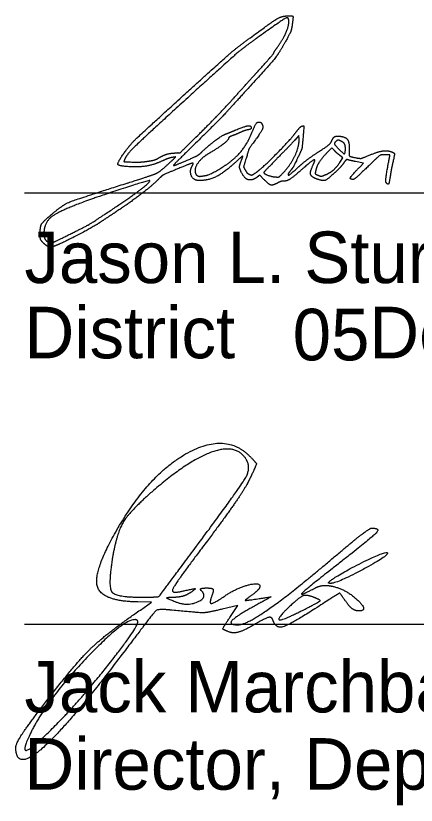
# Model space of a CAD drawing. Extents: x 0 to 34, y 0 to 22.
# Drawn here: x 24.504 to 25.591, y 6.891 to 9.036 of the extents above; entities that cross this region are included whole.
import ezdxf

# ---------------------------------------------------------------- set-up
doc = ezdxf.new("R2010")
doc.units = 0
doc.layers.add('SH_Data', color=7, linetype='Continuous')
doc.layers.add('SH_Text', color=7, linetype='Continuous')

msp = doc.modelspace()

# ---------------------------------------------------------------- linework, layer by layer
at = {"layer": 'SH_Data'}
for p, q in [((24.5279, 8.555), (28.0279, 8.555)), ((24.5279, 7.3828), (28.0279, 7.3828))]:
    msp.add_line(p, q, dxfattribs=at)
for points in [[(25.2734, 8.7013), (25.273, 8.7106), (25.2619, 8.698)], [(25.3691, 8.6693), (25.3619, 8.6764), (25.3504, 8.6648)], [(25.3841, 8.6372), (25.3926, 8.6498), (25.3844, 8.656)], [(25.4388, 8.6256), (25.4485, 8.6356), (25.4269, 8.6396)], [(25.1778, 8.5911), (25.1667, 8.6023), (25.1597, 8.5972)]]:
    msp.add_lwpolyline(points, dxfattribs=at)
for points in [[(25.1411, 8.976), (25.2022, 9.0209), (25.2243, 9.0342), (25.2391, 9.0353)], [(25.2391, 9.0353), (25.2552, 9.0364), (25.2579, 9.0321), (25.2546, 9.0104)], [(25.2456, 9.0172), (25.2463, 9.0338), (25.2292, 9.0255), (25.1595, 8.9754)], [(25.2164, 8.9529), (25.2294, 8.9713), (25.2451, 9.0058), (25.2456, 9.0172)], [(25.2546, 9.0104), (25.2526, 8.9974), (25.2484, 8.9869), (25.2367, 8.9657)], [(24.9691, 8.8279), (25.0673, 8.9172), (25.1035, 8.9484), (25.1411, 8.976)], [(25.1595, 8.9754), (25.1187, 8.9461), (25.0918, 8.9228), (24.971, 8.8127)], [(25.2367, 8.9657), (25.2185, 8.933), (25.1947, 8.9036), (25.1193, 8.8209)], [(25.2052, 8.9357), (25.2052, 8.9365), (25.2102, 8.9443), (25.2164, 8.9529)], [(25.162, 8.8853), (25.193, 8.9196), (25.2051, 8.9338), (25.2052, 8.9357)], [(25.097, 8.8131), (25.119, 8.8375), (25.1482, 8.87), (25.162, 8.8853)], [(24.7957, 8.6591), (24.813, 8.6839), (24.8466, 8.7166), (24.9691, 8.8279)], [(25.1193, 8.8209), (25.0669, 8.7635), (25.0507, 8.7468), (24.966, 8.6635)], [(24.971, 8.8127), (24.8453, 8.698), (24.8051, 8.6585), (24.7992, 8.6437)], [(25.0037, 8.7159), (25.0331, 8.745), (25.0751, 8.7887), (25.097, 8.8131)], [(25.1021, 8.7257), (25.1264, 8.7357), (25.1438, 8.7379), (25.1435, 8.7309)], [(25.1435, 8.7309), (25.1435, 8.7289), (25.1396, 8.7266), (25.1348, 8.7258)], [(25.1415, 8.7093), (25.1539, 8.7382), (25.1595, 8.7472), (25.1653, 8.7469)], [(25.1731, 8.7411), (25.1765, 8.7339), (25.1706, 8.7202), (25.154, 8.6974)], [(25.1653, 8.7469), (25.1681, 8.7468), (25.1716, 8.7442), (25.1731, 8.7411)], [(25.2642, 8.7182), (25.2711, 8.7277), (25.2791, 8.7357), (25.2818, 8.7361)], [(25.2818, 8.7361), (25.2864, 8.7368), (25.2865, 8.735), (25.2841, 8.7058)], [(24.9393, 8.6629), (24.95, 8.6631), (24.9518, 8.6646), (25.0037, 8.7159)], [(25.0104, 8.6665), (25.025, 8.6808), (25.0633, 8.71), (25.0717, 8.7133)], [(25.0717, 8.7133), (25.0754, 8.7147), (25.089, 8.7203), (25.1021, 8.7257)], [(25.0919, 8.7096), (25.0864, 8.7076), (25.0818, 8.7042), (25.0817, 8.702)], [(25.0866, 8.6391), (25.1054, 8.6537), (25.1326, 8.6884), (25.1415, 8.7093)], [(25.114, 8.7187), (25.1074, 8.7156), (25.0974, 8.7115), (25.0919, 8.7096)], [(25.1348, 8.7258), (25.13, 8.725), (25.1207, 8.7218), (25.114, 8.7187)], [(25.1572, 8.6103), (25.1742, 8.6224), (25.2494, 8.6982), (25.2642, 8.7182)], [(25.0817, 8.702), (25.0815, 8.6976), (25.0512, 8.6746), (25.0275, 8.6609)], [(25.154, 8.6974), (25.1378, 8.6748), (25.1372, 8.6737), (25.1295, 8.6477)], [(25.2619, 8.698), (25.2558, 8.6911), (25.2344, 8.6688), (25.2143, 8.6485)], [(25.2303, 8.6089), (25.2502, 8.6297), (25.2743, 8.6813), (25.2734, 8.7013)], [(25.2841, 8.7058), (25.2819, 8.6795), (25.2803, 8.672), (25.2736, 8.6579)], [(25.3259, 8.6658), (25.3463, 8.6789), (25.3589, 8.6889), (25.3608, 8.6932)], [(25.3608, 8.6932), (25.3654, 8.7038), (25.3718, 8.7089), (25.3801, 8.7086)], [(25.3751, 8.6956), (25.3685, 8.6906), (25.3699, 8.6852), (25.3808, 8.6739)], [(25.3865, 8.6952), (25.3808, 8.698), (25.3783, 8.698), (25.3751, 8.6956)], [(25.3801, 8.7086), (25.3986, 8.7077), (25.4105, 8.692), (25.4095, 8.6694)], [(25.399, 8.6707), (25.3995, 8.6823), (25.3949, 8.6914), (25.3865, 8.6952)], [(24.9662, 8.6417), (24.9904, 8.6519), (25.0024, 8.6587), (25.0104, 8.6665)], [(25.3844, 8.656), (25.3799, 8.6594), (25.373, 8.6654), (25.3691, 8.6693)], [(25.3808, 8.6739), (25.3932, 8.661), (25.3985, 8.6601), (25.399, 8.6707)], [(25.4095, 8.6694), (25.4089, 8.6557), (25.4119, 8.6528), (25.4302, 8.6494)], [(25.4615, 8.6558), (25.4842, 8.6653), (25.5103, 8.6704), (25.5207, 8.6673)], [(25.5207, 8.6673), (25.5314, 8.6641), (25.5329, 8.6579), (25.5279, 8.6374)], [(24.8141, 8.6254), (24.7844, 8.6268), (24.7795, 8.6357), (24.7957, 8.6591)], [(24.862, 8.6403), (24.874, 8.642), (24.8866, 8.6458), (24.8922, 8.6493)], [(24.8922, 8.6493), (24.9043, 8.6567), (24.925, 8.6627), (24.9393, 8.6629)], [(24.9294, 8.6508), (24.9243, 8.6501), (24.9117, 8.6456), (24.9013, 8.6409)], [(24.9167, 8.6315), (24.9384, 8.6519), (24.9385, 8.6521), (24.9294, 8.6508)], [(24.966, 8.6635), (24.947, 8.6448), (24.9318, 8.6291), (24.9322, 8.6286)], [(25.0275, 8.6609), (25.0116, 8.6517), (24.9915, 8.6268), (24.991, 8.6158)], [(25.1201, 8.6541), (25.1194, 8.6541), (25.1111, 8.647), (25.1018, 8.6383)], [(25.1172, 8.6433), (25.1196, 8.6492), (25.1209, 8.654), (25.1201, 8.6541)], [(25.1295, 8.6477), (25.1228, 8.6252), (25.1228, 8.6247), (25.1273, 8.6162)], [(25.2143, 8.6485), (25.1943, 8.6281), (25.1778, 8.6107), (25.1778, 8.6097)], [(25.2736, 8.6579), (25.2599, 8.6289), (25.2569, 8.6233), (25.2501, 8.615)], [(25.2713, 8.6244), (25.2837, 8.6358), (25.3083, 8.6544), (25.3259, 8.6658)], [(25.3504, 8.6648), (25.3355, 8.6496), (25.3216, 8.628), (25.3188, 8.6158)], [(25.404, 8.6453), (25.4031, 8.6461), (25.3989, 8.6417), (25.3945, 8.6355)], [(25.4269, 8.6396), (25.4151, 8.6418), (25.4048, 8.6444), (25.404, 8.6453)], [(25.4302, 8.6494), (25.4395, 8.6478), (25.4448, 8.6488), (25.4615, 8.6558)], [(25.5124, 8.658), (25.4968, 8.6587), (25.4885, 8.6534), (25.4564, 8.6222)], [(25.5107, 8.5809), (25.5079, 8.5839), (25.5106, 8.6075), (25.5183, 8.6479)], [(25.5183, 8.6479), (25.5201, 8.6573), (25.5198, 8.6577), (25.5124, 8.658)], [(24.7992, 8.6437), (24.7975, 8.6396), (24.7995, 8.6391), (24.8194, 8.6382)], [(24.9013, 8.6409), (24.8791, 8.6308), (24.8415, 8.6241), (24.8141, 8.6254)], [(24.8194, 8.6382), (24.8315, 8.6377), (24.8507, 8.6386), (24.862, 8.6403)], [(24.8827, 8.6061), (24.8898, 8.609), (24.9037, 8.6194), (24.9167, 8.6315)], [(24.9322, 8.6286), (24.9327, 8.6281), (24.948, 8.634), (24.9662, 8.6417)], [(24.9858, 8.6353), (24.9852, 8.636), (24.9663, 8.629), (24.9438, 8.6197)], [(24.9998, 8.5882), (24.9859, 8.5888), (24.9755, 8.6146), (24.9836, 8.6283)], [(24.9836, 8.6283), (24.9855, 8.6314), (24.9865, 8.6346), (24.9858, 8.6353)], [(25.1018, 8.6383), (25.0706, 8.6093), (25.0254, 8.5871), (24.9998, 8.5882)], [(25.0203, 8.6018), (25.0293, 8.6033), (25.0697, 8.626), (25.0866, 8.6391)], [(25.1159, 8.6122), (25.1114, 8.6219), (25.1118, 8.6298), (25.1172, 8.6433)], [(25.2434, 8.6054), (25.2432, 8.6005), (25.2513, 8.6061), (25.2713, 8.6244)], [(25.3161, 8.643), (25.3163, 8.6469), (25.2987, 8.634), (25.2745, 8.6124)], [(25.3206, 8.5926), (25.306, 8.5981), (25.3028, 8.612), (25.3117, 8.6308)], [(25.3117, 8.6308), (25.3141, 8.6359), (25.3161, 8.6414), (25.3161, 8.643)], [(25.3447, 8.6036), (25.3584, 8.6094), (25.3746, 8.6233), (25.3841, 8.6372)], [(25.3945, 8.6355), (25.3901, 8.6292), (25.3787, 8.6168), (25.369, 8.608)], [(25.4205, 8.5909), (25.4101, 8.5914), (25.4155, 8.6014), (25.4388, 8.6256)], [(25.5279, 8.6374), (25.5255, 8.6275), (25.5225, 8.6116), (25.5211, 8.6022)], [(24.8065, 8.5809), (24.8418, 8.5921), (24.876, 8.6035), (24.8827, 8.6061)], [(24.9438, 8.6197), (24.9089, 8.6054), (24.9012, 8.6011), (24.8906, 8.5903)], [(24.991, 8.6158), (24.9907, 8.6074), (24.9994, 8.5984), (25.0068, 8.5996)], [(25.0068, 8.5996), (25.0101, 8.6001), (25.0162, 8.6011), (25.0203, 8.6018)], [(25.1597, 8.5972), (25.1452, 8.5868), (25.1244, 8.5939), (25.1159, 8.6122)], [(25.1273, 8.6162), (25.1298, 8.6114), (25.1349, 8.6063), (25.1387, 8.6048)], [(25.1387, 8.6048), (25.1444, 8.6025), (25.1473, 8.6033), (25.1572, 8.6103)], [(25.1778, 8.6097), (25.1776, 8.6066), (25.1992, 8.5983), (25.2093, 8.5977)], [(25.2093, 8.5977), (25.2175, 8.5972), (25.2205, 8.5987), (25.2303, 8.6089)], [(25.2745, 8.6124), (25.2558, 8.5957), (25.2387, 8.5859), (25.2289, 8.5862)], [(25.2501, 8.615), (25.2464, 8.6105), (25.2434, 8.6062), (25.2434, 8.6054)], [(25.3188, 8.6158), (25.3168, 8.6072), (25.3173, 8.6057), (25.3227, 8.6033)], [(25.369, 8.608), (25.3494, 8.59), (25.3375, 8.5862), (25.3206, 8.5926)], [(25.3227, 8.6033), (25.3314, 8.5994), (25.3347, 8.5994), (25.3447, 8.6036)], [(25.4564, 8.6222), (25.4386, 8.6049), (25.4225, 8.5908), (25.4205, 8.5909)], [(25.5211, 8.6022), (25.5183, 8.5825), (25.5152, 8.576), (25.5107, 8.5809)], [(24.5994, 8.4942), (24.6315, 8.5217), (24.668, 8.537), (24.8065, 8.5809)], [(24.8679, 8.5877), (24.8666, 8.5892), (24.7361, 8.5471), (24.6935, 8.5315)], [(24.751, 8.4997), (24.8107, 8.5391), (24.8709, 8.5845), (24.8679, 8.5877)], [(24.8906, 8.5903), (24.8749, 8.5743), (24.8094, 8.5243), (24.7741, 8.5013)], [(25.2148, 8.5812), (25.2018, 8.5743), (25.1919, 8.577), (25.1778, 8.5911)], [(25.2289, 8.5862), (25.2264, 8.5863), (25.2201, 8.584), (25.2148, 8.5812)], [(24.6935, 8.5315), (24.6234, 8.5058), (24.582, 8.4749), (24.5808, 8.4471)], [(24.6461, 8.4395), (24.6974, 8.4651), (24.7074, 8.4708), (24.751, 8.4997)], [(24.7741, 8.5013), (24.7592, 8.4916), (24.7398, 8.4787), (24.7311, 8.4727)], [(24.5703, 8.4476), (24.571, 8.4642), (24.5786, 8.4764), (24.5994, 8.4942)], [(24.7311, 8.4727), (24.7163, 8.4626), (24.6301, 8.4176), (24.6125, 8.4109)], [(24.5836, 8.4144), (24.5741, 8.4226), (24.5696, 8.4336), (24.5703, 8.4476)], [(24.5808, 8.4471), (24.5802, 8.434), (24.5903, 8.4194), (24.6004, 8.4188)], [(24.6004, 8.4188), (24.6025, 8.4186), (24.623, 8.4279), (24.6461, 8.4395)], [(24.6125, 8.4109), (24.6012, 8.4066), (24.5912, 8.4078), (24.5836, 8.4144)]]:
    msp.add_open_spline(points, degree=2, dxfattribs=at)
at = {"layer": 'SH_Text'}
for p, q in [((24.9902, 7.5879), (24.9902, 7.5879)), ((25.3555, 7.498), (25.3555, 7.498)), ((25.3107, 7.4564), (25.3107, 7.4564))]:
    msp.add_line(p, q, dxfattribs=at)
for points in [[(24.8425, 7.4209), (24.8732, 7.4421), (24.8354, 7.4428)], [(25.0855, 7.4011), (25.1067, 7.4334), (25.0649, 7.4233)]]:
    msp.add_lwpolyline(points, dxfattribs=at)
for points in [[(24.7789, 7.6386), (24.8651, 7.789), (25.0732, 7.905), (25.1389, 7.8394)], [(25.1299, 7.8302), (25.104, 7.8722), (24.9779, 7.831), (24.8825, 7.7494)], [(24.9902, 7.5879), (25.1115, 7.7513), (25.144, 7.8075), (25.1299, 7.8302)], [(25.1389, 7.8394), (25.1577, 7.8206), (25.1577, 7.8155), (25.1394, 7.7771)], [(25.1394, 7.7771), (25.1284, 7.7541), (25.0767, 7.6786), (25.0245, 7.6092)], [(24.8825, 7.7494), (24.8159, 7.6924), (24.7771, 7.6283), (24.766, 7.557)], [(24.8354, 7.4428), (24.7375, 7.4445), (24.7141, 7.5256), (24.7789, 7.6386)], [(25.369, 7.5651), (25.4194, 7.608), (25.4649, 7.6432), (25.4701, 7.6433)], [(25.4701, 7.6433), (25.495, 7.6438), (25.4716, 7.6182), (25.3857, 7.5509)], [(25.0245, 7.6092), (24.9722, 7.5399), (24.9295, 7.4792), (24.9295, 7.4744)], [(24.844, 7.4559), (24.8907, 7.4559), (24.8953, 7.4601), (24.9902, 7.5879)], [(25.3555, 7.498), (25.3759, 7.5159), (25.5079, 7.5816), (25.5131, 7.5765)], [(25.5131, 7.5765), (25.5193, 7.5703), (25.3767, 7.4934), (25.359, 7.4934)], [(24.766, 7.557), (24.7545, 7.4837), (24.776, 7.4559), (24.844, 7.4559)], [(25.1076, 7.3809), (25.1307, 7.3809), (25.2567, 7.4698), (25.369, 7.5651)], [(25.3857, 7.5509), (25.2925, 7.4779), (25.271, 7.4564), (25.315, 7.4799)], [(25.0736, 7.4603), (25.1025, 7.4801), (25.167, 7.4976), (25.167, 7.4857)], [(25.315, 7.4799), (25.3276, 7.4866), (25.3515, 7.4887), (25.3681, 7.4845)], [(25.359, 7.4934), (25.3542, 7.4934), (25.3526, 7.4955), (25.3555, 7.498)], [(24.9295, 7.4744), (24.9295, 7.4696), (24.9449, 7.4693), (24.9638, 7.4737)], [(24.9795, 7.469), (24.9692, 7.462), (24.9495, 7.4559), (24.9357, 7.4553)], [(24.9399, 7.4427), (24.9698, 7.4307), (25.026, 7.4553), (25.0086, 7.4727)], [(24.9638, 7.4737), (24.9894, 7.4796), (24.9934, 7.4784), (24.9795, 7.469)], [(25.0086, 7.4727), (25.004, 7.4772), (25.0103, 7.4809), (25.0225, 7.4809)], [(25.0225, 7.4809), (25.037, 7.4809), (25.0422, 7.4745), (25.0375, 7.4622)], [(25.167, 7.4857), (25.167, 7.4812), (25.1572, 7.4703), (25.1453, 7.4616)], [(25.4011, 7.4431), (25.3843, 7.4672), (25.3822, 7.4667), (25.3165, 7.4244)], [(25.3681, 7.4845), (25.4042, 7.4754), (25.4625, 7.4184), (25.4358, 7.4184)], [(24.9357, 7.4553), (24.9133, 7.4545), (24.9138, 7.4531), (24.9399, 7.4427)], [(25.0375, 7.4622), (25.0285, 7.4389), (25.0414, 7.4383), (25.0736, 7.4603)], [(25.1453, 7.4616), (25.1264, 7.4478), (25.1284, 7.4465), (25.161, 7.4514)], [(25.161, 7.4514), (25.1977, 7.457), (25.1976, 7.4567), (25.1522, 7.4316)], [(25.3107, 7.4564), (25.2935, 7.4627), (25.277, 7.4576), (25.2576, 7.4398)], [(25.2826, 7.4201), (25.329, 7.4437), (25.3325, 7.4483), (25.3107, 7.4564)], [(24.9237, 7.421), (24.8903, 7.4243), (24.8786, 7.4138), (24.8019, 7.3122)], [(25.0649, 7.4233), (25.0246, 7.4136), (25.0023, 7.4132), (24.9237, 7.421)], [(25.1522, 7.4316), (25.1011, 7.4034), (25.0814, 7.3809), (25.1076, 7.3809)], [(25.3165, 7.4244), (25.2476, 7.38), (25.2101, 7.3703), (25.202, 7.3946)], [(25.2576, 7.4398), (25.2133, 7.3993), (25.2246, 7.3904), (25.2826, 7.4201)], [(25.4358, 7.4184), (25.4262, 7.4184), (25.4106, 7.4295), (25.4011, 7.4431)], [(24.5916, 7.1787), (24.6692, 7.2792), (24.7493, 7.3565), (24.8425, 7.4209)], [(25.0843, 7.361), (25.0661, 7.368), (25.0662, 7.3716), (25.0855, 7.4011)], [(25.202, 7.3946), (25.1991, 7.4032), (25.1799, 7.398), (25.1508, 7.3808)], [(24.8354, 7.3917), (24.8145, 7.4126), (24.596, 7.1869), (24.5497, 7.0966)], [(24.6198, 7.1153), (24.6874, 7.1844), (24.8431, 7.384), (24.8354, 7.3917)], [(25.1508, 7.3808), (25.1252, 7.3657), (25.0953, 7.3568), (25.0843, 7.361)], [(24.8019, 7.3122), (24.6496, 7.1101), (24.5045, 6.9815), (24.5045, 7.0485)], [(24.5045, 7.0485), (24.5045, 7.0581), (24.5437, 7.1167), (24.5916, 7.1787)], [(24.5497, 7.0966), (24.5184, 7.0356), (24.55, 7.0441), (24.6198, 7.1153)]]:
    msp.add_open_spline(points, degree=2, dxfattribs=at)

# ---------------------------------------------------------------- texts
for s, p in [('Jason L. Sturgeon, P.E.', (24.5279, 8.3094)), ('District       Deputy Director', (24.5279, 8.105)), ('              05', (24.5279, 8.0994)), ('Jack Marchbanks, PhD', (24.5279, 7.1428)), ('Director, Department of Transportation', (24.5279, 6.9328))]:
    msp.add_text(s, height=0.14, dxfattribs=at).set_placement(p)

doc.saveas('drawing.dxf')
